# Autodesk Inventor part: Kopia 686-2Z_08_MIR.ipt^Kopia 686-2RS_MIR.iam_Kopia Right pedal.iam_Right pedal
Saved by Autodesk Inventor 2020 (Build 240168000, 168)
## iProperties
Created: 2017-10
Part Number: Kopia 686-2Z_08_MIR.ipt^Kopia 686-2RS_MIR.iam_Kopia Right pedal.iam_Right pedal
Material: Ogólny
Document SubType Name: Modeling
Designer: Tomasz
Density: 1 g/cm^3
Appearance: Domyślna
Sending System: SolidWorks 2017
Last Author: Tomasz
Last Saved: 2017-10-01
Author: Tomasz
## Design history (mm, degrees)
